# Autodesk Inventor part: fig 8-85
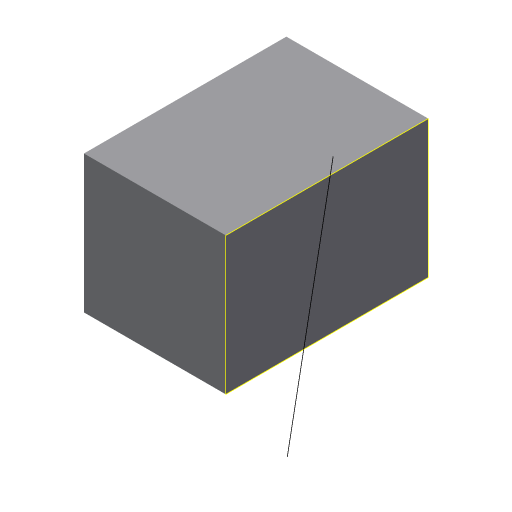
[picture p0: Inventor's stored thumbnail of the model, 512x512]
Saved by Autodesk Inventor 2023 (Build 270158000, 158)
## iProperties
Created: 2009-04
Part Number: fig 8-85
Document SubType Name: Modeling
Designer: Sham
Density: 1 g/cm^3
Material: Generic
Appearance: Default
Author: Sham
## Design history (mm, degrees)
sketch "Sketch5"
  geometry: L1 (14, -13.6)-(0, -13.6); L2 (0, -13.6)-(0, 0); L3 (0, 0)-(14, 0); L4 (14, 0)-(14, -13.6)
  constraints: 8 end point
extrude "Extrusion2" new body sketch "Sketch5" distance "d3" = 20; taper "d4" = 0 deg
sketch "Sketch7"
  geometry: L1 (13.6, 20)-(0, 20) reference; L2 (0, 0)-(0, 20) reference; L3 (13.6, 0)-(0, 0) reference; L4 (13.6, 0)-(13.6, 20) reference; L5 (-1.442, 10.604)-(21.986, 6.075)
  constraints: 2 end point
body "Solid2"
